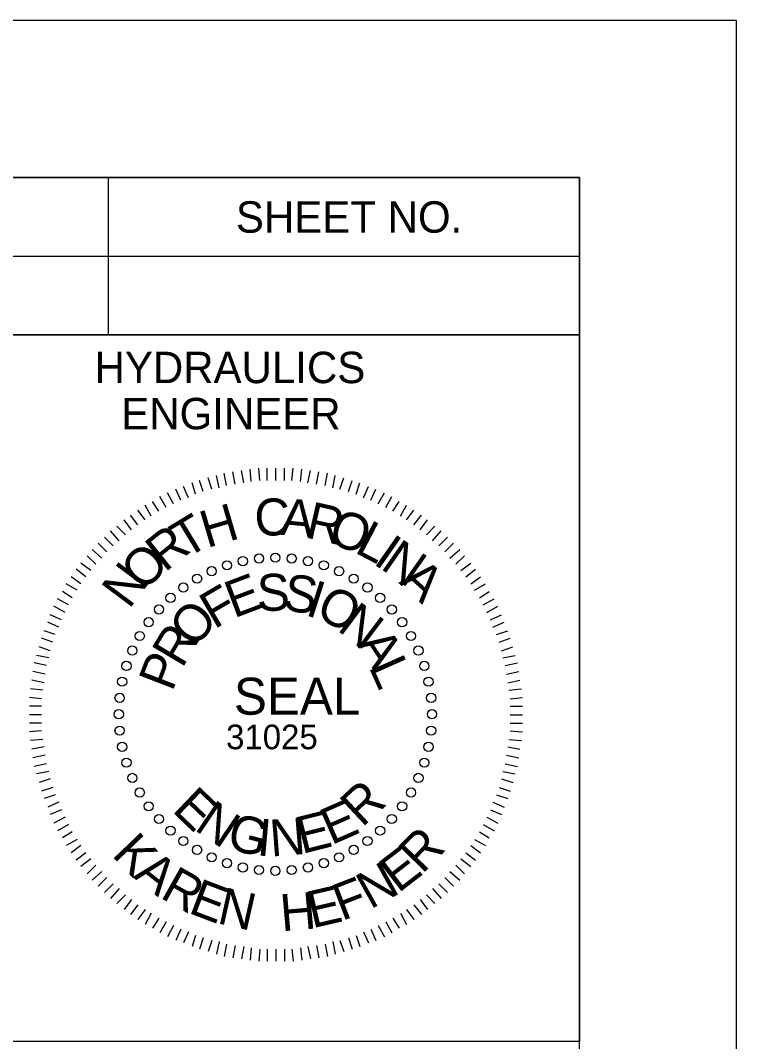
# Model space of a CAD drawing. Extents: x 573078 to 573116.9, y -55221.3 to -55199.3.
# Drawn here: x 573109.734 to 573112.014, y -55202.549 to -55199.298 of the extents above; entities that cross this region are included whole.
import ezdxf

# ---------------------------------------------------------------- set-up
doc = ezdxf.new("R2010")
doc.units = 0
for name, color, linetype in [('Old_Level_5', 7, 'Continuous'), ('Scratch_Level_1', 7, 'Continuous'), ('Sheet Plot Border Inside CELL', 7, 'Continuous'), ('Sheet Profile CELL', 7, 'Continuous')]:
    doc.layers.add(name, color=color, linetype=linetype)

msp = doc.modelspace()

# ---------------------------------------------------------------- linework, layer by layer
at = {"layer": 'Old_Level_5'}
for p, q in [((573110.3904, -55200.7787), (573110.3829, -55200.7393)), ((573110.4179, -55200.775), (573110.4104, -55200.7356)), ((573110.4454, -55200.7706), (573110.4379, -55200.7318)), ((573110.4691, -55200.7668), (573110.4654, -55200.7275)), ((573110.4966, -55200.7631), (573110.4929, -55200.7237)), ((573110.5204, -55200.7631), (573110.5204, -55200.7237)), ((573110.5479, -55200.7631), (573110.5479, -55200.7237)), ((573110.5479, -55200.7631), (573110.5479, -55200.7237)), ((573110.5479, -55200.7631), (573110.5479, -55200.7237)), ((573110.5479, -55200.7631), (573110.5479, -55200.7237)), ((573110.5479, -55200.7631), (573110.5479, -55200.7237)), ((573110.5479, -55200.7631), (573110.5479, -55200.7237)), ((573110.5479, -55200.7631), (573110.5479, -55200.7237)), ((573110.5479, -55200.7631), (573110.5479, -55200.7237)), ((573110.5479, -55200.7631), (573110.5479, -55200.7237)), ((573110.5479, -55200.7631), (573110.5479, -55200.7237)), ((573110.5479, -55200.7631), (573110.5479, -55200.7237)), ((573110.5479, -55200.7631), (573110.5479, -55200.7237)), ((573110.5479, -55200.7631), (573110.5479, -55200.7237)), ((573110.5479, -55200.7631), (573110.5479, -55200.7237)), ((573110.5479, -55200.7631), (573110.5479, -55200.7237)), ((573110.5479, -55200.7631), (573110.5479, -55200.7237)), ((573110.5479, -55200.7631), (573110.5479, -55200.7237)), ((573110.5479, -55200.7631), (573110.5479, -55200.7237)), ((573110.5479, -55200.7631), (573110.5479, -55200.7237)), ((573110.5479, -55200.7631), (573110.5479, -55200.7237)), ((573110.5479, -55200.7631), (573110.5479, -55200.7237)), ((573110.5479, -55200.7631), (573110.5479, -55200.7237)), ((573110.5479, -55200.7631), (573110.5479, -55200.7237)), ((573110.5479, -55200.7631), (573110.5479, -55200.7237)), ((573110.5479, -55200.7631), (573110.5479, -55200.7237)), ((573110.5479, -55200.7631), (573110.5479, -55200.7237)), ((573110.5479, -55200.7631), (573110.5479, -55200.7237)), ((573110.5479, -55200.7631), (573110.5479, -55200.7237)), ((573110.5479, -55200.7631), (573110.5479, -55200.7237)), ((573110.5479, -55200.7631), (573110.5479, -55200.7237)), ((573110.5754, -55200.7631), (573110.5754, -55200.7237)), ((573110.5985, -55200.7631), (573110.6029, -55200.7237)), ((573110.626, -55200.7668), (573110.6304, -55200.7275)), ((573110.6497, -55200.7706), (573110.6579, -55200.7318)), ((573110.6772, -55200.775), (573110.6847, -55200.7356)), ((573110.7047, -55200.7787), (573110.7122, -55200.7393)), ((573110.2922, -55200.8062), (573110.281, -55200.7706)), ((573110.316, -55200.7981), (573110.3041, -55200.7631)), ((573110.3435, -55200.7906), (573110.3316, -55200.755)), ((573110.3672, -55200.7868), (573110.3591, -55200.7475)), ((573110.7285, -55200.7868), (573110.736, -55200.7475)), ((573110.7516, -55200.7906), (573110.7635, -55200.755)), ((573110.7791, -55200.7981), (573110.791, -55200.7631)), ((573110.8029, -55200.8062), (573110.8147, -55200.7706)), ((573110.2216, -55200.8375), (573110.2022, -55200.8025)), ((573110.2454, -55200.8256), (573110.2297, -55200.7906)), ((573110.2691, -55200.8181), (573110.2535, -55200.7825)), ((573110.8266, -55200.8181), (573110.8422, -55200.7825)), ((573110.8497, -55200.8256), (573110.8654, -55200.7906)), ((573110.8735, -55200.8375), (573110.8929, -55200.8025)), ((573110.151, -55200.8768), (573110.1316, -55200.8412)), ((573110.1747, -55200.8612), (573110.1554, -55200.83)), ((573110.1985, -55200.8493), (573110.1785, -55200.8143)), ((573110.8972, -55200.8493), (573110.9166, -55200.8143)), ((573110.9204, -55200.8612), (573110.9404, -55200.83)), ((573110.9441, -55200.8768), (573110.9635, -55200.8412)), ((573110.1079, -55200.9043), (573110.0847, -55200.8731)), ((573110.1316, -55200.8887), (573110.1079, -55200.8575)), ((573110.9635, -55200.8887), (573110.9872, -55200.8575)), ((573110.9872, -55200.9043), (573111.011, -55200.8731)), ((573110.0885, -55200.92), (573110.0647, -55200.8887)), ((573111.0072, -55200.92), (573111.0304, -55200.8887)), ((573110.0491, -55200.9556), (573110.0216, -55200.9237)), ((573110.0685, -55200.9356), (573110.041, -55200.9081)), ((573111.0266, -55200.9356), (573111.0541, -55200.9081)), ((573111.046, -55200.9556), (573111.0735, -55200.9237)), ((573110.0097, -55200.9906), (573109.9822, -55200.9631)), ((573110.0297, -55200.9712), (573110.0022, -55200.9437)), ((573111.066, -55200.9712), (573111.0935, -55200.9437)), ((573111.0854, -55200.9906), (573111.1129, -55200.9631)), ((573109.9747, -55201.03), (573109.9472, -55201.0025)), ((573109.9941, -55201.0106), (573109.9629, -55200.9831)), ((573111.101, -55201.0106), (573111.1329, -55200.9831)), ((573111.121, -55201.03), (573111.1485, -55201.0025)), ((573109.9591, -55201.0493), (573109.9272, -55201.0262)), ((573111.1366, -55201.0493), (573111.1679, -55201.0262)), ((573109.9272, -55201.0925), (573109.896, -55201.0693)), ((573109.9429, -55201.0693), (573109.9116, -55201.0456)), ((573111.1522, -55201.0693), (573111.1835, -55201.0456)), ((573111.1679, -55201.0925), (573111.1991, -55201.0693)), ((573109.9154, -55201.1125), (573109.8804, -55201.0925)), ((573111.1797, -55201.1125), (573111.2147, -55201.0925)), ((573109.8997, -55201.1362), (573109.8685, -55201.1162)), ((573111.1954, -55201.1362), (573111.2266, -55201.1162)), ((573109.8766, -55201.1831), (573109.841, -55201.1637)), ((573109.8879, -55201.1593), (573109.8529, -55201.14)), ((573111.2072, -55201.1593), (573111.2422, -55201.14)), ((573111.2191, -55201.1831), (573111.2541, -55201.1637)), ((573109.8647, -55201.2068), (573109.8291, -55201.1906)), ((573111.231, -55201.2068), (573111.266, -55201.1906)), ((573109.8566, -55201.23), (573109.8216, -55201.2143)), ((573111.2385, -55201.23), (573111.2741, -55201.2143)), ((573109.8447, -55201.2537), (573109.8097, -55201.2418)), ((573111.2504, -55201.2537), (573111.286, -55201.2418)), ((573109.8291, -55201.305), (573109.7941, -55201.2931)), ((573109.8372, -55201.2775), (573109.8016, -55201.2656)), ((573111.2585, -55201.2775), (573111.2935, -55201.2656)), ((573111.266, -55201.305), (573111.3016, -55201.2931)), ((573109.8254, -55201.3281), (573109.786, -55201.3206)), ((573111.2697, -55201.3281), (573111.3091, -55201.3206)), ((573109.8172, -55201.3518), (573109.7785, -55201.3437)), ((573111.2779, -55201.3518), (573111.3172, -55201.3437)), ((573109.8135, -55201.3793), (573109.7741, -55201.3712)), ((573111.2816, -55201.3793), (573111.321, -55201.3712)), ((573109.806, -55201.4306), (573109.7666, -55201.4262)), ((573109.8097, -55201.4068), (573109.7704, -55201.3987)), ((573111.286, -55201.4068), (573111.3247, -55201.3987)), ((573111.2897, -55201.4306), (573111.3291, -55201.4262)), ((573109.8016, -55201.4581), (573109.7629, -55201.4537)), ((573111.2935, -55201.4581), (573111.3329, -55201.4537)), ((573109.8016, -55201.4812), (573109.7629, -55201.4812)), ((573111.2935, -55201.4812), (573111.3329, -55201.4812)), ((573109.8016, -55201.5087), (573109.7629, -55201.5087)), ((573111.2935, -55201.5087), (573111.3329, -55201.5087)), ((573109.8016, -55201.5362), (573109.7629, -55201.5362)), ((573111.2935, -55201.5362), (573111.3329, -55201.5362)), ((573109.8016, -55201.56), (573109.7629, -55201.5637)), ((573109.806, -55201.5875), (573109.7666, -55201.5912)), ((573111.2897, -55201.5875), (573111.3291, -55201.5912)), ((573111.2935, -55201.56), (573111.3329, -55201.5637)), ((573109.8097, -55201.6106), (573109.7704, -55201.6187)), ((573111.286, -55201.6106), (573111.3247, -55201.6187)), ((573109.8135, -55201.6381), (573109.7741, -55201.6462)), ((573111.2816, -55201.6381), (573111.321, -55201.6462)), ((573109.8172, -55201.6656), (573109.7785, -55201.6737)), ((573111.2779, -55201.6656), (573111.3172, -55201.6737)), ((573109.8254, -55201.6893), (573109.786, -55201.6975)), ((573109.8291, -55201.7131), (573109.7941, -55201.725)), ((573111.266, -55201.7131), (573111.3016, -55201.725)), ((573111.2697, -55201.6893), (573111.3091, -55201.6975)), ((573109.8372, -55201.7406), (573109.8016, -55201.7525)), ((573111.2585, -55201.7406), (573111.2935, -55201.7525)), ((573109.8447, -55201.7637), (573109.8097, -55201.7756)), ((573111.2504, -55201.7637), (573111.286, -55201.7756)), ((573109.8566, -55201.7875), (573109.8216, -55201.8031)), ((573109.8647, -55201.8112), (573109.8291, -55201.8268)), ((573111.231, -55201.8112), (573111.266, -55201.8268)), ((573111.2385, -55201.7875), (573111.2741, -55201.8031)), ((573109.8766, -55201.835), (573109.841, -55201.8543)), ((573111.2191, -55201.835), (573111.2541, -55201.8543)), ((573109.8879, -55201.8581), (573109.8529, -55201.8781)), ((573109.8997, -55201.8818), (573109.8685, -55201.9012)), ((573111.1954, -55201.8818), (573111.2266, -55201.9012)), ((573111.2072, -55201.8581), (573111.2422, -55201.8781)), ((573109.9154, -55201.9056), (573109.8804, -55201.925)), ((573111.1797, -55201.9056), (573111.2147, -55201.925)), ((573109.9272, -55201.925), (573109.896, -55201.9487)), ((573111.1679, -55201.925), (573111.1991, -55201.9487)), ((573109.9429, -55201.9487), (573109.9116, -55201.9718)), ((573109.9591, -55201.9681), (573109.9272, -55201.9918)), ((573111.1366, -55201.9681), (573111.1679, -55201.9918)), ((573111.1522, -55201.9487), (573111.1835, -55201.9718)), ((573109.9747, -55201.9881), (573109.9472, -55202.015)), ((573109.9941, -55202.0075), (573109.9629, -55202.035)), ((573111.101, -55202.0075), (573111.1329, -55202.035)), ((573111.121, -55201.9881), (573111.1485, -55202.015)), ((573110.0097, -55202.0268), (573109.9822, -55202.0543)), ((573111.0854, -55202.0268), (573111.1129, -55202.0543)), ((573110.0297, -55202.0468), (573110.0022, -55202.0743)), ((573110.0491, -55202.0625), (573110.0216, -55202.0937)), ((573111.046, -55202.0625), (573111.0735, -55202.0937)), ((573111.066, -55202.0468), (573111.0935, -55202.0743)), ((573110.0685, -55202.0818), (573110.041, -55202.1093)), ((573110.0885, -55202.0975), (573110.0647, -55202.1293)), ((573111.0072, -55202.0975), (573111.0304, -55202.1293)), ((573111.0266, -55202.0818), (573111.0541, -55202.1093)), ((573110.1079, -55202.1137), (573110.0847, -55202.145)), ((573110.1316, -55202.1293), (573110.1079, -55202.1606)), ((573110.151, -55202.1406), (573110.1316, -55202.1762)), ((573110.9441, -55202.1406), (573110.9635, -55202.1762)), ((573110.9635, -55202.1293), (573110.9872, -55202.1606)), ((573110.9872, -55202.1137), (573111.011, -55202.145)), ((573110.1747, -55202.1568), (573110.1554, -55202.1881)), ((573110.1985, -55202.1681), (573110.1785, -55202.2037)), ((573110.8972, -55202.1681), (573110.9166, -55202.2037)), ((573110.9204, -55202.1568), (573110.9404, -55202.1881)), ((573110.2216, -55202.18), (573110.2022, -55202.2156)), ((573110.2454, -55202.1918), (573110.2297, -55202.2275)), ((573110.2691, -55202.2), (573110.2535, -55202.235)), ((573110.8266, -55202.2), (573110.8422, -55202.235)), ((573110.8497, -55202.1918), (573110.8654, -55202.2275)), ((573110.8735, -55202.18), (573110.8929, -55202.2156)), ((573110.2922, -55202.2118), (573110.281, -55202.2468)), ((573110.316, -55202.2193), (573110.3041, -55202.255)), ((573110.3435, -55202.2275), (573110.3316, -55202.2625)), ((573110.3672, -55202.2312), (573110.3591, -55202.2706)), ((573110.3904, -55202.2393), (573110.3829, -55202.2781)), ((573110.7047, -55202.2393), (573110.7122, -55202.2781)), ((573110.7285, -55202.2312), (573110.736, -55202.2706)), ((573110.7516, -55202.2275), (573110.7635, -55202.2625)), ((573110.7791, -55202.2193), (573110.791, -55202.255)), ((573110.8029, -55202.2118), (573110.8147, -55202.2468)), ((573110.4179, -55202.2431), (573110.4104, -55202.2825)), ((573110.4454, -55202.2468), (573110.4379, -55202.2862)), ((573110.4691, -55202.2506), (573110.4654, -55202.29)), ((573110.4966, -55202.255), (573110.4929, -55202.2937)), ((573110.5204, -55202.255), (573110.5204, -55202.2937)), ((573110.5479, -55202.255), (573110.5479, -55202.2937)), ((573110.5754, -55202.255), (573110.5754, -55202.2937)), ((573110.5985, -55202.255), (573110.6029, -55202.2937)), ((573110.626, -55202.2506), (573110.6304, -55202.29)), ((573110.6497, -55202.2468), (573110.6579, -55202.2862)), ((573110.6772, -55202.2431), (573110.6847, -55202.2825))]:
    msp.add_line(p, q, dxfattribs=at)
for centre in [(573110.4939, -55201.0115), (573110.4939, -55201.0115), (573110.546, -55201.0088), (573110.546, -55201.0088), (573110.5981, -55201.0115), (573110.3432, -55201.0519), (573110.3432, -55201.0519), (573110.392, -55201.0332), (573110.392, -55201.0332), (573110.4424, -55201.0197), (573110.4424, -55201.0197), (573110.6497, -55201.0197), (573110.7001, -55201.0332), (573110.7488, -55201.0519), (573110.2968, -55201.0756), (573110.2968, -55201.0756), (573110.7953, -55201.0756), (573110.253, -55201.104), (573110.253, -55201.104), (573110.8391, -55201.104), (573110.2124, -55201.1369), (573110.2124, -55201.1369), (573110.8796, -55201.1369), (573110.1755, -55201.1738), (573110.1755, -55201.1738), (573110.9165, -55201.1738), (573110.1427, -55201.2143), (573110.1427, -55201.2143), (573110.9494, -55201.2143), (573110.1143, -55201.2581), (573110.1143, -55201.2581), (573110.9778, -55201.2581), (573110.0906, -55201.3046), (573110.0906, -55201.3046), (573111.0015, -55201.3046), (573110.0719, -55201.3533), (573110.0719, -55201.3533), (573111.0202, -55201.3533), (573110.0584, -55201.4037), (573110.0584, -55201.4037), (573111.0337, -55201.4037), (573110.0502, -55201.4552), (573110.0502, -55201.4552), (573111.0418, -55201.4552), (573110.0475, -55201.5073), (573110.0475, -55201.5073), (573111.0446, -55201.5073), (573110.0502, -55201.5595), (573110.0502, -55201.5595), (573111.0418, -55201.5595), (573110.0584, -55201.611), (573110.0584, -55201.611), (573111.0337, -55201.611), (573110.0719, -55201.6614), (573110.0719, -55201.6614), (573111.0202, -55201.6614), (573110.0906, -55201.7101), (573110.0906, -55201.7101), (573111.0015, -55201.7101), (573110.1143, -55201.7566), (573110.1143, -55201.7566), (573110.9778, -55201.7566), (573110.1427, -55201.8004), (573110.1427, -55201.8004), (573110.9494, -55201.8004), (573110.1755, -55201.8409), (573110.1755, -55201.8409), (573110.9165, -55201.8409), (573110.2124, -55201.8778), (573110.2124, -55201.8778), (573110.8796, -55201.8778), (573110.253, -55201.9107), (573110.253, -55201.9107), (573110.8391, -55201.9107), (573110.2968, -55201.9391), (573110.2968, -55201.9391), (573110.7953, -55201.9391), (573110.3432, -55201.9628), (573110.3432, -55201.9628), (573110.392, -55201.9815), (573110.392, -55201.9815), (573110.7001, -55201.9815), (573110.7488, -55201.9628), (573110.4424, -55201.995), (573110.4424, -55201.995), (573110.4939, -55202.0032), (573110.4939, -55202.0032), (573110.546, -55202.0059), (573110.5981, -55202.0032), (573110.6497, -55201.995)]:
    msp.add_circle(centre, 0.0147, dxfattribs=at)
at = {"layer": 'Scratch_Level_1'}
msp.add_line((573110.547, -55201.5087), (573110.547, -55201.5087), dxfattribs=at)
at = {"layer": 'Sheet Plot Border Inside CELL'}
msp.add_lwpolyline([(573112.0142, -55199.2984), (573078.0142, -55199.2984), (573078.0142, -55221.2984), (573112.0142, -55221.2984)], close=True, dxfattribs=at)
at = {"layer": 'Sheet Profile CELL'}
for p, q in [((573110.0142, -55199.7994), (573110.0142, -55200.2994)), ((573107.5142, -55200.0494), (573111.5142, -55200.0494))]:
    msp.add_line(p, q, dxfattribs=at)
for points in [[(573111.5142, -55199.7984), (573081.5142, -55199.7984), (573081.5142, -55220.7984), (573111.5142, -55220.7984)], [(573107.5142, -55199.7984), (573111.5142, -55199.7984), (573111.5142, -55200.2994), (573107.5142, -55200.2994)], [(573109.5142, -55200.2994), (573111.5142, -55200.2994), (573111.5142, -55202.5494), (573109.5142, -55202.5494)]]:
    msp.add_lwpolyline(points, close=True, dxfattribs=at)

# ---------------------------------------------------------------- texts
at = {"layer": 'Old_Level_5'}
for s, height, rotation, p in [('H', 0.1178, 16.5355, (573110.3279, -55200.9787)), ('C', 0.1178, 1.8409, (573110.481, -55200.94)), ('A', 0.1178, 354.4936, (573110.5591, -55200.9356)), ('R', 0.1173, 347.1464, (573110.6379, -55200.9437)), ('T', 0.1178, 31.23, (573110.261, -55201.0143)), ('O', 0.1178, 339.7991, (573110.7085, -55200.9593)), ('L', 0.1173, 332.4518, (573110.7947, -55200.9906)), ('R', 0.1178, 38.5773, (573110.1941, -55201.0575)), ('I', 0.1178, 325.1046, (573110.8541, -55201.0262)), ('N', 0.1178, 325.1046, (573110.8772, -55201.0418)), ('O', 0.1178, 45.9246, (573110.1279, -55201.12)), ('N', 0.1178, 53.2718, (573110.0804, -55201.175)), ('A', 0.1178, 317.7573, (573110.9366, -55201.0887)), ('E', 0.1178, 20.7502, (573110.4141, -55201.2025)), ('S', 0.1178, 1.4893, (573110.4885, -55201.1793)), ('S', 0.1178, 351.8588, (573110.5672, -55201.175)), ('F', 0.1173, 30.3806, (573110.3516, -55201.2381)), ('I', 0.1178, 342.2284, (573110.6379, -55201.1906)), ('O', 0.1178, 332.5979, (573110.6691, -55201.195)), ('O', 0.1178, 49.6415, (573110.2885, -55201.3006)), ('N', 0.1178, 322.9675, (573110.7397, -55201.2381)), ('R', 0.1178, 59.272, (573110.2491, -55201.3637)), ('A', 0.1178, 303.7066, (573110.8029, -55201.285)), ('P', 0.1178, 68.9024, (573110.2179, -55201.4381)), ('L', 0.1178, 294.0761, (573110.8422, -55201.3556)), ('E', 0.1178, 316.3156, (573110.2141, -55201.815)), ('R', 0.1178, 42.9896, (573110.8222, -55201.87)), ('N', 0.1178, 325.946, (573110.2847, -55201.8737)), ('E', 0.1173, 23.7287, (573110.7241, -55201.925)), ('E', 0.1178, 14.0983, (573110.6304, -55201.9525)), ('G', 0.1178, 345.2069, (573110.3866, -55201.9331)), ('I', 0.1178, 354.8374, (573110.4847, -55201.9562)), ('N', 0.1173, 4.4678, (573110.5322, -55201.9606)), ('R', 0.1175, 45.7969, (573111.0136, -55202.018)), ('K', 0.1175, 313.7767, (573110.0225, -55201.9562)), ('E', 0.1175, 37.6963, (573110.9371, -55202.0785)), ('A', 0.1175, 321.8774, (573110.0908, -55202.0257)), ('N', 0.1175, 29.1693, (573110.8484, -55202.1299)), ('R', 0.1175, 330.6886, (573110.1754, -55202.0896)), ('E', 0.1175, 339.2155, (573110.2656, -55202.1385)), ('F', 0.1175, 21.0687, (573110.7578, -55202.1661)), ('N', 0.1175, 347.3161, (573110.3572, -55202.1719)), ('H', 0.1175, 4.8675, (573110.5661, -55202.1986)), ('E', 0.1175, 12.9681, (573110.6631, -55202.1891))]:
    msp.add_text(s, height=height, rotation=rotation, dxfattribs=at).set_placement(p)
for s, height, p in [('SEAL', 0.11777, (573110.4141, -55201.5087)), ('31025', 0.0785, (573110.3891, -55201.6187))]:
    msp.add_text(s, height=height, dxfattribs=at).set_placement(p)
at = {"layer": 'Sheet Profile CELL'}
for s, p in [('SHEET NO.', (573110.4204, -55199.9742)), ('HYDRAULICS', (573109.9704, -55200.4532)), ('ENGINEER', (573110.0554, -55200.6002))]:
    msp.add_text(s, height=0.1, dxfattribs=at).set_placement(p)

doc.saveas('drawing.dxf')
